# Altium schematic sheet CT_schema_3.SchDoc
size 298 x 159 mm
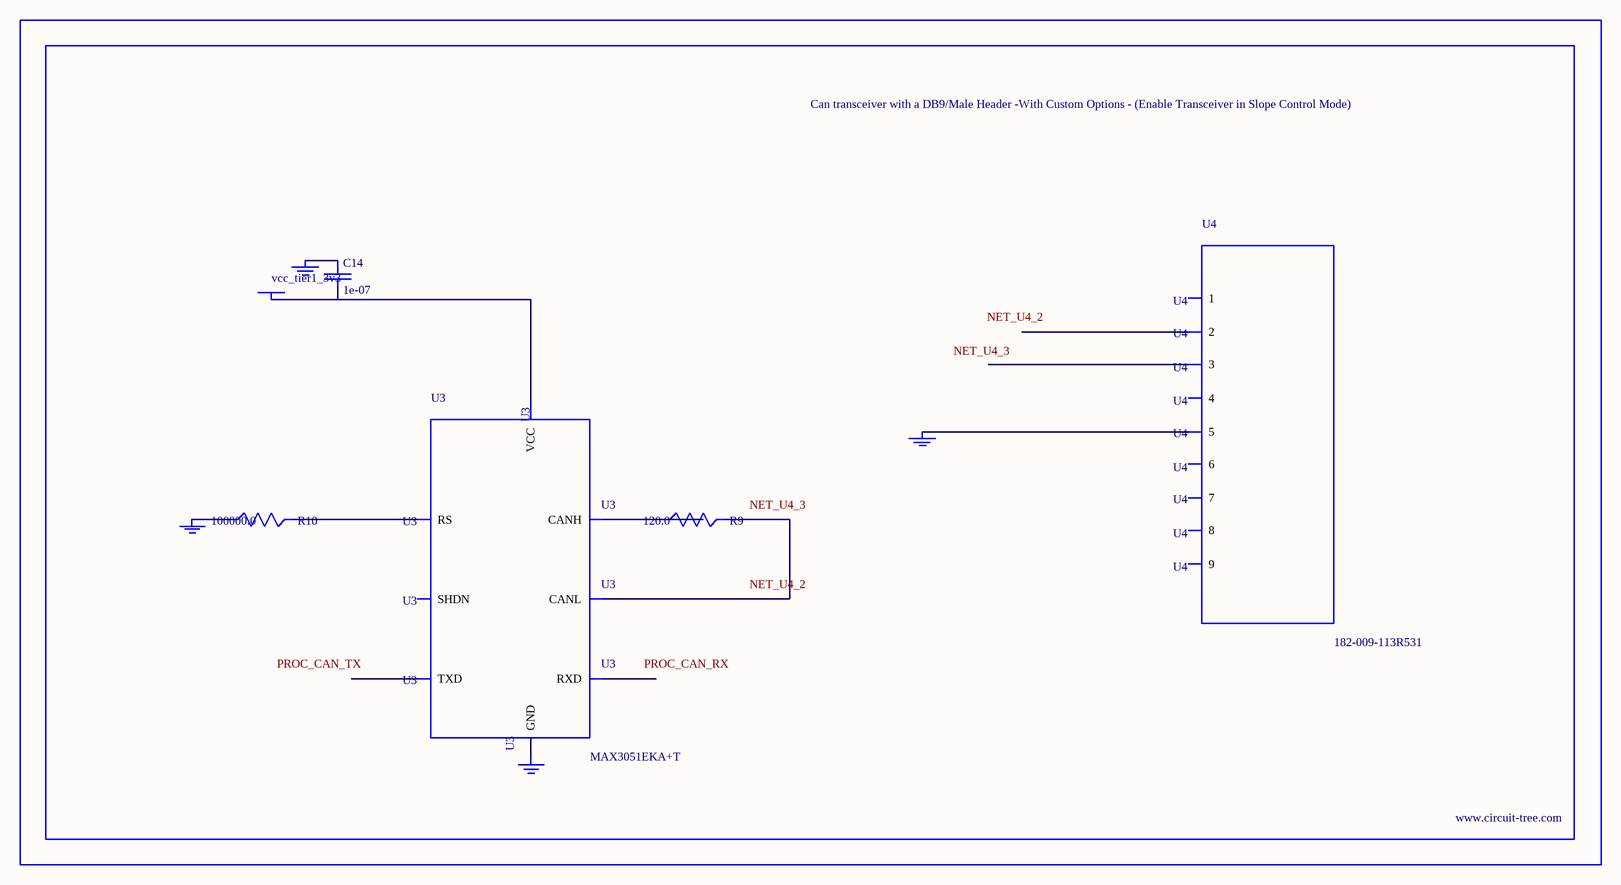
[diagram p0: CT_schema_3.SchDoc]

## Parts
BORDER2  (no value)
C14  1e-07  [C0402]
GND_INSTANCE_2_0  (no value)
GND_INSTANCE_2_1  (no value)
GND_INSTANCE_2_2  (no value)
GND_INSTANCE_2_3  (no value)
POWER_INSTANCE_2_0  vcc_tier1_3v3
R9  120.0  [R0603]
R10  100000.0  [R0603]
U3  MAX3051EKA+T  [SOT-23-8]
U4  182-009-113R531  [182-009-MALE]

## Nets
NetC14_1: C14.1 GND_INSTANCE_2_0.0(GND)
NetC14_2: C14.2 POWER_INSTANCE_2_0.0(PWR) U3.3(VCC)
NetGND_INSTANCE_2_1_0: GND_INSTANCE_2_1.0(GND) R10.1
NetGND_INSTANCE_2_2_0: GND_INSTANCE_2_2.0(GND) U3.2(GND)
NetGND_INSTANCE_2_3_0: GND_INSTANCE_2_3.0(GND) U4.5
NetR9_1: R9.1 U3.7(CANH)
NetR9_2: R9.2 U3.6(CANL)
NetR10_2: R10.2 U3.8(RS)

Not connected (* = marked no-connect by the designer): U3 1(TXD) 4(RXD) 5(SHDN); U4 1 2 3 4 6 7 8 9

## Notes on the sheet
- Labels drawn without touching a wire or pin: NET_U4_2, NET_U4_3, PROC_CAN_RX, PROC_CAN_TX

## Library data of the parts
BORDER2 = BORDER_PAGE2
C14 = C0402C104K3RACTU
GND_INSTANCE_2_0-GND_INSTANCE_2_3 = GND
POWER_INSTANCE_2_0 = PWR
R9 = RC0603JR-07120RL
R10 = RC0603JR-07100KL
